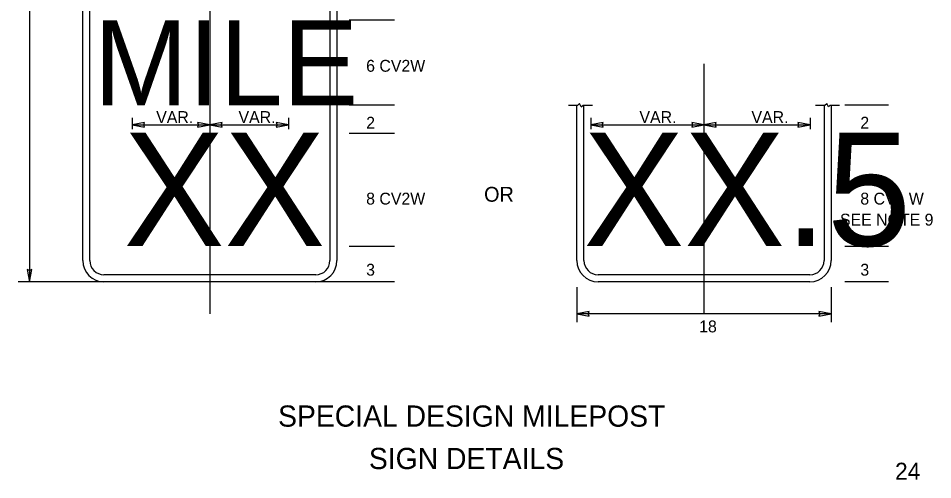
# Model space of a CAD drawing. Extents: x 56108 to 56738, y 11696 to 12112.
# Drawn here: x 56521.6 to 56737.4, y 11706.5 to 11815.3 of the extents above; entities that cross this region are included whole.
import ezdxf

# ---------------------------------------------------------------- set-up
doc = ezdxf.new("R2010")
doc.units = 0
for name, color, linetype in [('CL_dp', 7, 'Continuous'), ('GSDims', 7, 'Continuous'), ('SignPanel', 7, 'Continuous'), ('TextMisc', 7, 'Continuous'), ('TextShtNo', 7, 'Continuous')]:
    doc.layers.add(name, color=color, linetype=linetype)

msp = doc.modelspace()

# ---------------------------------------------------------------- linework, layer by layer
at = {"layer": 'CL_dp'}
for p, q in [((56566.81, 11917.97), (56566.81, 11745.62)), ((56683.41, 11804.56), (56683.41, 11745.62))]:
    msp.add_line(p, q, dxfattribs=at)
at = {"layer": 'GSDims'}
for p, q in [((56524.22, 11913.16), (56524.22, 11753.16)), ((56610.35, 11814.82), (56599.67, 11814.82)), ((56610.35, 11794.82), (56599.67, 11794.82)), ((56726.96, 11794.82), (56716.67, 11794.82)), ((56548.51, 11791.85), (56548.51, 11789.16)), ((56551.41, 11790.74), (56548.51, 11790.2)), ((56548.51, 11790.2), (56566.81, 11790.2)), ((56548.51, 11790.2), (56551.41, 11789.64)), ((56551.19, 11790.2), (56551.41, 11790.74)), ((56551.41, 11789.64), (56551.19, 11790.2)), ((56566.81, 11790.2), (56563.91, 11790.76)), ((56563.91, 11790.76), (56564.13, 11790.2)), ((56564.13, 11790.2), (56563.91, 11789.66)), ((56563.91, 11789.66), (56566.81, 11790.2)), ((56569.71, 11790.74), (56566.81, 11790.2)), ((56566.81, 11790.2), (56585.39, 11790.2)), ((56566.81, 11790.2), (56569.71, 11789.64)), ((56569.49, 11790.2), (56569.71, 11790.74)), ((56569.71, 11789.64), (56569.49, 11790.2)), ((56585.39, 11790.2), (56582.49, 11790.76)), ((56582.49, 11790.76), (56582.71, 11790.2)), ((56582.71, 11790.2), (56582.49, 11789.66)), ((56582.49, 11789.66), (56585.39, 11790.2)), ((56585.39, 11791.85), (56585.39, 11789.16)), ((56656.74, 11791.85), (56656.74, 11789.16)), ((56659.64, 11790.74), (56656.74, 11790.2)), ((56656.74, 11790.2), (56683.41, 11790.2)), ((56656.74, 11790.2), (56659.64, 11789.64)), ((56659.42, 11790.2), (56659.64, 11790.74)), ((56659.64, 11789.64), (56659.42, 11790.2)), ((56683.41, 11790.2), (56680.51, 11790.76)), ((56680.51, 11790.76), (56680.73, 11790.2)), ((56680.73, 11790.2), (56680.51, 11789.66)), ((56680.51, 11789.66), (56683.41, 11790.2)), ((56686.31, 11790.74), (56683.41, 11790.2)), ((56683.41, 11790.2), (56708.43, 11790.2)), ((56683.41, 11790.2), (56686.31, 11789.64)), ((56686.09, 11790.2), (56686.31, 11790.74)), ((56686.31, 11789.64), (56686.09, 11790.2)), ((56708.43, 11790.2), (56705.53, 11790.76)), ((56705.53, 11790.76), (56705.75, 11790.2)), ((56705.75, 11790.2), (56705.53, 11789.66)), ((56705.53, 11789.66), (56708.43, 11790.2)), ((56708.43, 11791.85), (56708.43, 11789.16)), ((56610.35, 11788.16), (56599.67, 11788.16)), ((56726.96, 11788.16), (56716.67, 11788.16)), ((56610.35, 11761.49), (56599.67, 11761.49)), ((56726.96, 11761.49), (56716.67, 11761.49)), ((56524.22, 11755.84), (56523.68, 11756.06)), ((56523.68, 11756.06), (56524.22, 11753.16)), ((56524.22, 11753.16), (56524.78, 11756.06)), ((56524.78, 11756.06), (56524.22, 11755.84)), ((56534.73, 11753.16), (56521.6, 11753.16)), ((56610.35, 11753.16), (56527.07, 11753.16)), ((56653.41, 11751.92), (56653.41, 11743.69)), ((56713.41, 11751.92), (56713.41, 11743.69)), ((56726.96, 11753.16), (56716.67, 11753.16)), ((56656.31, 11746.16), (56653.41, 11745.62)), ((56713.41, 11745.62), (56653.41, 11745.62)), ((56653.41, 11745.62), (56656.31, 11745.06)), ((56656.09, 11745.62), (56656.31, 11746.16)), ((56656.31, 11745.06), (56656.09, 11745.62)), ((56713.41, 11745.62), (56710.51, 11746.18)), ((56710.51, 11746.18), (56710.73, 11745.62)), ((56710.73, 11745.62), (56710.51, 11745.08)), ((56710.51, 11745.08), (56713.41, 11745.62))]:
    msp.add_line(p, q, dxfattribs=at)
at = {"layer": 'SignPanel'}
for p, q in [((56651.41, 11794.82), (56653.63, 11794.82)), ((56653.63, 11794.82), (56654.04, 11795.24)), ((56654.45, 11794.41), (56654.04, 11795.24)), ((56654.45, 11794.41), (56654.87, 11794.82)), ((56654.87, 11794.82), (56657.08, 11794.82)), ((56709.75, 11794.82), (56711.96, 11794.82)), ((56711.96, 11794.82), (56712.37, 11795.24)), ((56712.79, 11794.41), (56712.37, 11795.24)), ((56712.79, 11794.41), (56713.2, 11794.82)), ((56713.2, 11794.82), (56715.41, 11794.82))]:
    msp.add_line(p, q, dxfattribs=at)
for points in [[(56536.81, 11758.16), (56536.81, 11908.16)], [(56538.48, 11758.16), (56538.48, 11908.16)], [(56595.14, 11908.16), (56595.14, 11758.16)], [(56596.81, 11908.16), (56596.81, 11758.16)], [(56653.41, 11758.16), (56653.41, 11794.82)], [(56655.08, 11758.16), (56655.08, 11794.82)], [(56711.75, 11794.82), (56711.75, 11758.16)], [(56713.41, 11794.82), (56713.41, 11758.16)], [(56591.81, 11754.82), (56541.81, 11754.82)], [(56708.41, 11754.82), (56658.41, 11754.82)], [(56591.81, 11753.16), (56541.81, 11753.16)], [(56708.41, 11753.16), (56658.41, 11753.16)]]:
    msp.add_lwpolyline(points, dxfattribs=at)
for centre, radius, start, end in [((56541.81, 11758.16), 5, 180, 270), ((56541.81, 11758.16), 3.33, 180, 270), ((56591.81, 11758.16), 5, 270, 360), ((56591.81, 11758.16), 3.33, 270, 360), ((56658.41, 11758.16), 5, 180, 270), ((56658.41, 11758.16), 3.33, 180, 270), ((56708.41, 11758.16), 5, 270, 360), ((56708.41, 11758.16), 3.33, 270, 360)]:
    msp.add_arc(centre, radius, start, end, dxfattribs=at)

# ---------------------------------------------------------------- texts
at = {"layer": 'GSDims'}
for s, height, p in [('6 CV2W', 2.8, (56603.69, 11802.69)), ('VAR.', 2.8, (56554.15, 11790.6)), ('VAR.', 2.8, (56573.57, 11790.6)), ('VAR.', 2.8, (56668.18, 11790.6)), ('VAR.', 2.8, (56694.61, 11790.6)), ('2', 2.8, (56603.69, 11789.27)), ('2', 2.8, (56720.3, 11789.27)), ('OR', 3.5, (56631.52, 11772.05)), ('8 CV2W', 2.8, (56603.69, 11771.38)), ('8 CV1 W', 2.8, (56720.3, 11771.38)), ('SEE NOTE 9', 2.8, (56715.5, 11766.42)), ('3', 2.8, (56603.69, 11754.62)), ('3', 2.8, (56720.3, 11754.62)), ('18', 2.8, (56682.27, 11741.25))]:
    msp.add_text(s, height=height, dxfattribs=at).set_placement(p)
at = {"layer": 'SignPanel'}
for s, height, p in [('MILE', 20, (56539.4, 11794.8)), ('XX', 26.667, (56546.46, 11761.63)), ('XX.5', 26.667, (56654.95, 11761.63))]:
    msp.add_text(s, height=height, dxfattribs=at).set_placement(p)
at = {"layer": 'TextMisc'}
for s, p in [('SPECIAL DESIGN MILEPOST ', (56582.9, 11719.02)), ('      SIGN DETAILS      ', (56593.19, 11709.02))]:
    msp.add_text(s, height=5, rotation=360, dxfattribs=at).set_placement(p)
at = {"layer": 'TextShtNo'}
msp.add_text('24', height=4, rotation=360, dxfattribs=at).set_placement((56728.5, 11706.52))

doc.saveas('drawing.dxf')
